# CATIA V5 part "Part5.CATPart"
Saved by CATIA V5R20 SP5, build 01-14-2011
Part number: Part1
Material "DS Red": density 7860 kg/m3, Young's modulus 2e+11 Pa, Poisson ratio 0.266
Bounding box of the stored display mesh (mm): x -25 to 25, y -25 to 27, z 0 to 110
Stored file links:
  E:\3.8\Part5.CATPart
  C:\Program Files\Dassault Systemes\B20\intel_a\startup\materials\Catalog.CATMaterial
  C:\Program Files\Dassault Systemes\B20\intel_a\startup\materials\blue_env_512x512.jpg
  C:\Program Files\Dassault Systemes\B20\intel_a\startup\materials\red_env_512x512.jpg
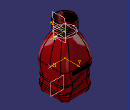
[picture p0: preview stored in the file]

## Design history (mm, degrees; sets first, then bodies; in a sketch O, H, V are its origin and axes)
Set1
  Sketch1 on xy-plane, origin (0, 0, 0), H (1, 0, 0), V (0, 1, 0)
    line L1 (25, 25) -> (25, -25)
    line L2 (25, -25) -> (-25, -25)
    line L3 (-25, -25) -> (-25, 25)
    line L4 (-25, 25) -> (25, 25)
    length L1 = 50
    length L4 = 50
    vertical: L1 V, L3 V
    horizontal: L2 H, L4 H
    equidistance: L1 L3 O, L2 L4 O
  Sketch2 on face of Pad1 from Sketch1.L2, origin (0, -25, 0), H (1, 0, 0), V (0, 0, 1)
    spline S1 through (-50, 40) (-10, 40) (11.1667, 31.1474) (61.1667, 41.1474)
  Extrude1: Element1 Sketch2, Lim1 500, Lim2 0
  MultiSel1: CommonCtxFeats ({extract ExtractElem face of Pad1 from Sketch1.L3}; {extract ExtractElem face of Fillet1}; {extract ExtractElem face of Pad1 from Sketch1.L4}; {extract ExtractElem face of Fillet1}; {extract ExtractElem face of Pad1 from Sketch1.L1}; {extract ExtractElem face of Fillet1}; {extract ExtractElem face of Pad1 from Sketch1.L2}; {extract ExtractElem face of Fillet1})
  Join1: Elements ({intersect ToIntersect1 {extract ExtractElem face of Pad1 from Sketch1.L3}, ToIntersect2 Extrude1}; {intersect ToIntersect1 {extract ExtractElem face of Fillet1}, ToIntersect2 Extrude1}; {intersect ToIntersect1 {extract ExtractElem face of Pad1 from Sketch1.L4}, ToIntersect2 Extrude1}; {intersect ToIntersect1 {extract ExtractElem face of Fillet1}, ToIntersect2 Extrude1}; {intersect ToIntersect1 {extract ExtractElem face of Pad1 from Sketch1.L1}, ToIntersect2 Extrude1}; {intersect ToIntersect1 {extract ExtractElem face of Fillet1}, ToIntersect2 Extrude1}; {intersect ToIntersect1 {extract ExtractElem face of Pad1 from Sketch1.L2}, ToIntersect2 Extrude1}; {intersect ToIntersect1 {extract ExtractElem face of Fillet1}, ToIntersect2 Extrude1})
  Plane1: type Normal, Curve Join1, RefPoint vertex [face of MultiSel1 | face of MultiSel1]
  Plane2: type Normal, Curve Join1, RefPoint vertex [face of MultiSel1 | face of MultiSel1]
  Circle1: type CtrRad, Start 0, End 180, Center vertex [face of MultiSel1 | face of MultiSel1], Support Plane2, Radius 1, FirstDirection (1, 0, 0)
Body1 (main body), material "DS Red"
  Pad1: profile Sketch1, direction (0, 0, 1), length 50
  Fillet1: on edge [face of Pad1 from Sketch1.L1 | face of Pad1 from Sketch1.L2]; edge [face of Pad1 from Sketch1.L2 | face of Pad1 from Sketch1.L3]; edge [face of Pad1 from Sketch1.L3 | face of Pad1 from Sketch1.L4]; edge [face of Pad1 from Sketch1.L4 | face of Pad1 from Sketch1.L1]
  Plane3: type Offset, RefPlane end face of Pad1, Offset 40, reversed
  Sketch3 on Plane3, origin (0, 0, 90), H (1, 0, 0), V (0, -1, 0)
    circle A1 centre (0, 0) radius 15
    radius A1 = 15
  Pad2: profile Sketch3, direction (0, 0, 1), length 20
  Fillet2: on edge [start face of Pad1 | face of Pad1 from Sketch1.L2]
  Sketch4 on end face of Pad1, origin (0, 0, 50), H (1, 0, 0), V (0, 1, 0)
    point P1 (25, 0)
    distance P1 V = 25
  Sketch5 on start face of Pad2, origin (0, 0, 90), H (1, 0, 0), V (0, -1, 0)
    point P1 (15, 0)
    distance P1 V = 15
  Loft1: solid, Sections ({boundary Boundary {extract ExtractElem end face of Pad1}}; edge [face of Pad2 from Sketch3.A1 | start face of Pad2]), StartFace end face of Pad1
  Slot1: profile Circle1, centre curve Join1
  Sketch6 on face of Pad1 from Sketch1.L2, origin (0, -25, 0), H (1, 0, 0), V (0, 0, 1)
    spline S1 through (-60.771, 20.3727) (-30, 30) (9.229, 20.3727) (70, 30)
  Extrude2: Element1 Sketch6, Lim1 500, Lim2 500
  MultiSel2: CommonCtxFeats ({extract ExtractElem face of Pad1 from Sketch1.L2}; {extract ExtractElem face of Fillet1}; {extract ExtractElem face of Pad1 from Sketch1.L3}; {extract ExtractElem face of Fillet1}; {extract ExtractElem face of Pad1 from Sketch1.L4}; {extract ExtractElem face of Fillet1}; {extract ExtractElem face of Pad1 from Sketch1.L1}; {extract ExtractElem face of Fillet1})
  Join2: Elements ({intersect ToIntersect1 {extract ExtractElem face of Pad1 from Sketch1.L2}, ToIntersect2 Extrude2}; {intersect ToIntersect1 {extract ExtractElem face of Fillet1}, ToIntersect2 Extrude2}; {intersect ToIntersect1 {extract ExtractElem face of Pad1 from Sketch1.L3}, ToIntersect2 Extrude2}; {intersect ToIntersect1 {extract ExtractElem face of Fillet1}, ToIntersect2 Extrude2}; {intersect ToIntersect1 {extract ExtractElem face of Pad1 from Sketch1.L4}, ToIntersect2 Extrude2}; {intersect ToIntersect1 {extract ExtractElem face of Fillet1}, ToIntersect2 Extrude2}; {intersect ToIntersect1 {extract ExtractElem face of Pad1 from Sketch1.L1}, ToIntersect2 Extrude2}; {intersect ToIntersect1 {extract ExtractElem face of Fillet1}, ToIntersect2 Extrude2})
  Plane4: type Normal, Curve Join2, RefPoint vertex [face of MultiSel2 | face of MultiSel2]
  Circle2: type CtrRad, Start 0, End 180, Center vertex [face of MultiSel2 | face of MultiSel2], Support Plane4, Radius 1, FirstDirection (0, 1, 0)
  Slot2: profile Circle2, centre curve Join2
  Shell1: ExtOffset 0, Face end face of Pad2, IntOffset 0.5
  Plane5: type Offset, RefPlane Plane3, Offset 3, reversed
  Sketch7 on xy-plane, origin (0, 0, 0), H (1, 0, 0), V (0, 1, 0)
  Sketch8 on Plane5, origin (0, 0, 93), H (1, 0, 0), V (0, -1, 0)
    point P1 (15, 0)
    distance P1 V = 15
    coincidence: P1 H
  Helix1: Direction Z axis, RefPoint Sketch8, Pitch 3, Height 15, TaperAngle 0
  Point1: type OnCurve, Support Helix1, RefPoint Sketch8, Length 5
  Sketch9 on face of Pad1 from Sketch1.L4, origin (0, 25, 0), H (-1, 0, 0), V (0, 0, 1)
    polyline C1
    polyline C2
    polyline C3
    polyline C4
    polyline C5
    polyline C6
    polyline C7
    polyline C8
    polyline C9
    polyline C10
    polyline C11
  Pad3: profile Sketch9, direction (0, 1, 0), length 2
  Line1: type PtDir, RefPoint Sketch8, Direction (1, 0, 0), Start 0, End 5
  Connect1: Curve1 Line1, Point1 vertex of Line1, Tension1 1, Curve2 Helix1, Point2 Point1, Tension2 1
  Point2: type OnCurve, Support Connect1, RefPoint vertex of Helix1, Length -5
  Line2: type PtDir, RefPoint vertex of Helix1, Direction (1, 0, 0), Start 0, End 5
  Connect2: Curve1 Connect1, Point1 Point2, Tension1 1, Curve2 Line2, Point2 vertex of Line2, Tension2 1
  Plane6: type Normal, Curve Connect2, RefPoint vertex of Connect2
  Plane7: type Normal, Curve Connect2, RefPoint vertex of Connect1
  Circle3: type CtrRad, Start 0, End 180, Radius 1, Center vertex of Connect2, Support Plane6, FirstDirection (0, -1, 0)
  Circle4: type CtrRad, Start 0, End 180, Radius 1, Center vertex of Connect1, Support Plane7, FirstDirection (0, 1, 0)
  Rib1: profile Circle3, centre curve Connect2
  Body2
    Sketch10 on Plane3, origin (0, 0, 90), H (1, 0, 0), V (0, -1, 0)
      circle A1 centre (0, 0.6598) radius 14
      point P1 (0, 0.6598)
      radius A1 = 14
      coincidence: P1 V
    Pad4: profile Sketch10, direction (0, 0, -1), length 30, mirrored extent
  Remove1: tool Body2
